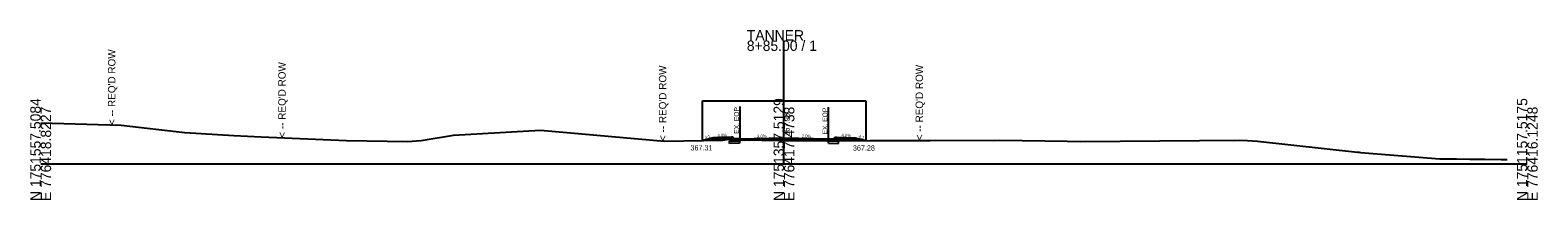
# Model space of a CAD drawing. Extents: x 774192 to 776597, y 1750236 to 1752784.
# Drawn here: x 774680.5 to 775086.2, y 1751248.9 to 1751294.6 of the extents above; entities that cross this region are included whole.
import ezdxf

# ---------------------------------------------------------------- set-up
doc = ezdxf.new("R2010")
doc.units = 0
for name, color, linetype in [('ControlPoints', 7, 'Continuous'), ('Default', 7, 'Continuous'), ('Observations', 7, 'Continuous'), ('Setups', 7, 'Continuous'), ('SHEET_BORDER_TX', 7, 'Continuous'), ('SHEET_DATE_DGN_TX', 7, 'Continuous'), ('SHEET_LOGO', 7, 'Continuous'), ('SHEET_PLOTTING_SHAPE', 7, 'Continuous'), ('SHEET_PRELIM', 7, 'Continuous'), ('SHEET_PROJ_NUMBER', 7, 'Continuous'), ('SHEET_TITLE_BLOCK_TX', 7, 'Continuous'), ('SHEET_WORK_NUMBER', 7, 'Continuous'), ('TS_BACKBONE', 7, 'Continuous'), ('TS_DIMENSIONS', 7, 'Continuous'), ('TS_SIDE_SLOPE_LT', 7, 'Continuous')]:
    doc.layers.add(name, color=color, linetype=linetype)

msp = doc.modelspace()

# ---------------------------------------------------------------- linework, layer by layer
at = {"layer": 'ControlPoints'}
msp.add_lwpolyline([(774683.33, 1751269.64), (774704.95, 1751268.98), (774722.09, 1751266.99), (774735.3, 1751266.19), (774742.68, 1751265.86), (774765.59, 1751264.87), (774781.99, 1751264.59), (774785.69, 1751264.88), (774794.37, 1751266.28), (774817.84, 1751267.64), (774851.16, 1751264.67), (774866.89, 1751264.99), (774869.16, 1751265.32), (774871.42, 1751265), (774883.33, 1751264.89), (774891.23, 1751264.84), (774893.19, 1751264.89), (774895.2, 1751264.81), (774896.45, 1751264.71), (774897.31, 1751264.77), (774906.41, 1751264.86), (774922.69, 1751264.89), (774941.4, 1751264.94), (774959.52, 1751264.68), (774963.14, 1751264.63), (775005.83, 1751264.94), (775008.08, 1751264.89), (775009.38, 1751264.8), (775010.73, 1751264.67), (775037.69, 1751261.72), (775038.11, 1751261.69), (775038.41, 1751261.67), (775059.77, 1751259.91), (775061.17, 1751259.94), (775064.25, 1751259.89), (775067.91, 1751259.86), (775071.92, 1751259.81), (775076.32, 1751259.74), (775077.88, 1751259.72)], dxfattribs=at)
at = {"layer": 'Default'}
for p, q in [((774871.34, 1751265.14), (774883.34, 1751265.38)), ((774883.33, 1751265.38), (774895.33, 1751265.14))]:
    msp.add_line(p, q, dxfattribs=at)
at = {"layer": 'Setups'}
for p, q in [((774883.33, 1751258.57), (774883.33, 1751291.78)), ((774683.33, 1751258.57), (774883.33, 1751258.57)), ((774883.33, 1751258.57), (775083.33, 1751258.57))]:
    msp.add_line(p, q, dxfattribs=at)
at = {"layer": 'SHEET_BORDER_TX'}
for p, q in [((774868.67, 1751264.09), (774868.67, 1751264.76)), ((774871.35, 1751264.14), (774868.67, 1751264.09)), ((774895.32, 1751264.14), (774898, 1751264.09)), ((774898, 1751264.09), (774898, 1751264.76))]:
    msp.add_line(p, q, dxfattribs=at)
for points in [[(774868.67, 1751264.76), (774871.33, 1751264.81), (774871.35, 1751264.14)], [(774895.32, 1751264.14), (774895.33, 1751264.81), (774898, 1751264.76)]]:
    msp.add_lwpolyline(points, dxfattribs=at)
at = {"layer": 'SHEET_LOGO'}
for p, q in [((774871.42, 1751274), (774871.42, 1751265)), ((774895.2, 1751273.81), (774895.2, 1751264.81))]:
    msp.add_line(p, q, dxfattribs=at)
at = {"layer": 'SHEET_PLOTTING_SHAPE'}
for p, q in [((774869.17, 1751264.77), (774869.17, 1751265.77)), ((774871.33, 1751264.81), (774869.17, 1751264.77)), ((774871.33, 1751265.31), (774871.33, 1751264.81)), ((774895.33, 1751265.31), (774895.33, 1751264.81)), ((774895.33, 1751264.81), (774897.5, 1751264.77)), ((774897.5, 1751264.77), (774897.5, 1751265.77))]:
    msp.add_line(p, q, dxfattribs=at)
at = {"layer": 'SHEET_PROJ_NUMBER'}
for p, q in [((774861.41, 1751264.88), (774861.41, 1751275.55)), ((774861.41, 1751275.55), (774905.37, 1751275.55)), ((774905.37, 1751275.55), (774905.37, 1751264.85))]:
    msp.add_line(p, q, dxfattribs=at)
at = {"layer": 'SHEET_TITLE_BLOCK_TX'}
for p, q in [((774864.17, 1751265.57), (774861.41, 1751264.88)), ((774869.17, 1751265.77), (774864.17, 1751265.57)), ((774869.67, 1751265.78), (774869.17, 1751265.77)), ((774869.67, 1751265.28), (774869.67, 1751265.78)), ((774871.33, 1751265.31), (774869.67, 1751265.28)), ((774871.33, 1751265.31), (774883.33, 1751265.55)), ((774883.33, 1751265.55), (774895.33, 1751265.31)), ((774895.33, 1751265.31), (774897, 1751265.28)), ((774897, 1751265.28), (774897, 1751265.78)), ((774897, 1751265.78), (774897.5, 1751265.77)), ((774897.5, 1751265.77), (774902.5, 1751265.57)), ((774902.5, 1751265.57), (774905.37, 1751264.85))]:
    msp.add_line(p, q, dxfattribs=at)
at = {"layer": 'SHEET_WORK_NUMBER'}
msp.add_line((774895.33, 1751264.8), (774895.33, 1751264.81), dxfattribs=at)
for points in [[(774871.33, 1751265.01), (774871.42, 1751265), (774877.83, 1751264.94)], [(774877.83, 1751264.94), (774883.33, 1751264.89), (774891.23, 1751264.84), (774893.19, 1751264.89), (774895.2, 1751264.81), (774895.33, 1751264.8)]]:
    msp.add_lwpolyline(points, dxfattribs=at)
at = {"layer": 'TS_BACKBONE'}
for p, q in [((774861.67, 1751264.94), (774861.67, 1751264.88)), ((774862.07, 1751265.04), (774862.07, 1751264.89)), ((774863, 1751265.27), (774863.17, 1751265.27)), ((774863.27, 1751265.34), (774863.27, 1751264.92)), ((774863.67, 1751265.44), (774863.67, 1751264.93)), ((774864.07, 1751265.54), (774864.07, 1751264.93)), ((774864.17, 1751265.27), (774865.17, 1751265.27)), ((774865.27, 1751265.61), (774865.27, 1751264.96)), ((774865.67, 1751265.63), (774865.67, 1751264.97)), ((774866.07, 1751265.64), (774866.07, 1751264.98)), ((774866.17, 1751265.27), (774867.17, 1751265.27)), ((774866.84, 1751265.67), (774867.17, 1751265.67)), ((774867.27, 1751265.69), (774867.27, 1751265.05)), ((774867.67, 1751265.71), (774867.67, 1751265.11)), ((774868.07, 1751265.72), (774868.07, 1751265.16)), ((774868.17, 1751265.67), (774869.17, 1751265.67)), ((774868.17, 1751265.27), (774868.87, 1751265.27)), ((774869.27, 1751265.77), (774869.27, 1751264.77)), ((774869.67, 1751265.28), (774869.67, 1751264.78)), ((774870.07, 1751265.29), (774870.07, 1751264.79)), ((774870.17, 1751265.27), (774871.17, 1751265.27)), ((774870.17, 1751264.87), (774871.17, 1751264.87)), ((774871.27, 1751265.31), (774871.27, 1751264.81)), ((774871.33, 1751264.91), (774871.43, 1751264.81)), ((774871.95, 1751264.82), (774872.46, 1751265.33)), ((774872.32, 1751265.33), (774872.81, 1751264.84)), ((774873.4, 1751264.85), (774873.91, 1751265.36)), ((774873.71, 1751265.36), (774874.2, 1751264.87)), ((774874.84, 1751264.88), (774875.35, 1751265.39)), ((774875.1, 1751265.39), (774875.59, 1751264.9)), ((774876.28, 1751264.91), (774876.79, 1751265.42)), ((774876.48, 1751265.41), (774876.97, 1751264.92)), ((774877.72, 1751264.94), (774878.23, 1751265.45)), ((774877.87, 1751265.44), (774878.37, 1751264.94)), ((774879.13, 1751264.93), (774879.68, 1751265.48)), ((774879.26, 1751265.47), (774879.8, 1751264.92)), ((774880.53, 1751264.92), (774881.12, 1751265.51)), ((774880.64, 1751265.5), (774881.23, 1751264.91)), ((774881.93, 1751264.91), (774882.56, 1751265.54)), ((774882.03, 1751265.53), (774882.65, 1751264.9)), ((774883.34, 1751264.89), (774883.98, 1751265.54)), ((774883.42, 1751265.55), (774884.08, 1751264.89)), ((774884.74, 1751264.88), (774885.37, 1751265.51)), ((774884.86, 1751265.52), (774885.5, 1751264.88)), ((774886.15, 1751264.88), (774886.75, 1751265.48)), ((774886.3, 1751265.49), (774886.92, 1751264.87)), ((774887.55, 1751264.87), (774888.14, 1751265.46)), ((774887.75, 1751265.46), (774888.35, 1751264.86)), ((774888.96, 1751264.86), (774889.53, 1751265.43)), ((774889.19, 1751265.43), (774889.77, 1751264.85)), ((774890.36, 1751264.85), (774890.91, 1751265.4)), ((774890.63, 1751265.41), (774891.19, 1751264.84)), ((774891.78, 1751264.86), (774892.3, 1751265.37)), ((774892.08, 1751265.38), (774892.58, 1751264.88)), ((774893.23, 1751264.89), (774893.69, 1751265.34)), ((774893.52, 1751265.35), (774894.01, 1751264.86)), ((774894.59, 1751264.83), (774895.07, 1751265.32)), ((774894.96, 1751265.32), (774895.33, 1751264.95)), ((774895.33, 1751265.27), (774895.5, 1751265.27)), ((774895.33, 1751264.87), (774895.5, 1751264.87)), ((774895.61, 1751265.31), (774895.61, 1751264.81)), ((774896.01, 1751265.3), (774896.01, 1751264.8)), ((774896.41, 1751265.29), (774896.41, 1751264.79)), ((774896.5, 1751265.27), (774897.5, 1751265.27)), ((774896.5, 1751264.87), (774897.5, 1751264.87)), ((774897, 1751265.78), (774897, 1751265.77)), ((774897, 1751265.67), (774897.5, 1751265.67)), ((774897.4, 1751265.77), (774897.4, 1751265.77)), ((774897.4, 1751264.77), (774897.4, 1751264.77)), ((774897.61, 1751265.76), (774897.61, 1751264.78)), ((774898.01, 1751265.75), (774898.01, 1751264.78)), ((774898.41, 1751265.73), (774898.41, 1751264.78)), ((774898.5, 1751265.67), (774899.5, 1751265.67)), ((774898.5, 1751265.27), (774899.5, 1751265.27)), ((774898.5, 1751264.87), (774899.5, 1751264.87)), ((774899.61, 1751265.68), (774899.61, 1751264.8)), ((774900.01, 1751265.67), (774900.01, 1751264.8)), ((774900.41, 1751265.65), (774900.41, 1751264.8)), ((774900.5, 1751265.27), (774901.5, 1751265.27)), ((774900.5, 1751264.87), (774901.5, 1751264.87)), ((774901.61, 1751265.6), (774901.61, 1751264.81)), ((774902.01, 1751265.59), (774902.01, 1751264.82)), ((774902.41, 1751265.57), (774902.41, 1751264.82)), ((774902.5, 1751265.27), (774903.5, 1751265.27)), ((774902.5, 1751264.87), (774903.5, 1751264.87)), ((774903.61, 1751265.29), (774903.61, 1751264.83)), ((774904.01, 1751265.19), (774904.01, 1751264.84)), ((774904.41, 1751265.09), (774904.41, 1751264.84)), ((774904.5, 1751264.87), (774905.27, 1751264.87))]:
    msp.add_line(p, q, dxfattribs=at)
at = {"layer": 'TS_SIDE_SLOPE_LT'}
msp.add_line((774897, 1751265.28), (774905.37, 1751264.85), dxfattribs=at)

# ---------------------------------------------------------------- texts
at = {"layer": 'Observations'}
for s, p in [('367.31', (774858.17, 1751262.18)), ('367.28', (774901.87, 1751262.15))]:
    msp.add_text(s, height=1.4, dxfattribs=at).set_placement(p)
at = {"layer": 'Setups'}
for s, p in [('TANNER', (774873.33, 1751291.78)), ('8+85.00 / 1', (774873.33, 1751288.98))]:
    msp.add_text(s, height=2.8, dxfattribs=at).set_placement(p)
for s, p in [('N 1751557.5084', (774683.33, 1751248.57)), ('N 1751357.5129', (774883.33, 1751248.57)), ('N 1751157.5175', (775083.33, 1751248.57)), ('E 776418.8227', (774686.13, 1751248.57)), ('E 776417.4738', (774886.13, 1751248.57)), ('E 776416.1248', (775086.13, 1751248.57))]:
    msp.add_text(s, height=2.8, rotation=90, dxfattribs=at).set_placement(p)
at = {"layer": 'SHEET_DATE_DGN_TX'}
for s, rotation, p in [('4:1', 14.0362, (774862.08, 1751265.25)), ('4.0%', 2.2906, (774865.44, 1751265.82)), ('2.0%', 1.1458, (774876.11, 1751265.61)), ('2.0%', 358.8542, (774888.11, 1751265.66)), ('4.0%', 357.7094, (774898.79, 1751265.92)), ('4:1', 345.9638, (774903.32, 1751265.57))]:
    msp.add_text(s, height=0.8, rotation=rotation, dxfattribs=at).set_placement(p)
at = {"layer": 'SHEET_LOGO'}
for p in [(774871.22, 1751266.68), (774895, 1751266.49)]:
    msp.add_text('EX. EOP', height=1.3, rotation=90, dxfattribs=at).set_placement(p)
at = {"layer": 'SHEET_PRELIM'}
msp.add_text(' 367.98', height=1.5, rotation=90, dxfattribs=at).set_placement((774884.83, 1751265.55))
at = {"layer": 'TS_DIMENSIONS'}
for p in [(774703.44, 1751269.06), (774749.25, 1751265.62), (774851.67, 1751264.71), (774920.74, 1751264.89)]:
    msp.add_text("< -- REQ'D ROW", height=2, rotation=90, dxfattribs=at).set_placement(p)

doc.saveas('drawing.dxf')
